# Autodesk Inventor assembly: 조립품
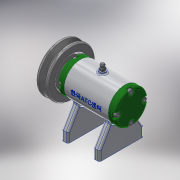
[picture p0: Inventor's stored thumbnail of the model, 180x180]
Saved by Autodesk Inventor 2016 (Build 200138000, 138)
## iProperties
Created: 2018-05
Part Number: 조립품
Material: 일반
Document SubType Name: Assembly
Designer: 201-25
Author: 201-25
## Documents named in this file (16)
- C:\Users\201-25\Desktop\480507V1001\답안조립품.iam
- C:\Users\201-25\Desktop\480507V1001\1-본체.ipt
- C:\Users\201-25\Desktop\480507V1001\베어링 6002.ipt
- C:\Users\201-25\Desktop\480507V1001\볼트 M4x12.ipt
- C:\Users\201-25\Desktop\480507V1001\볼트 M6x8.ipt
- C:\Users\201-25\Desktop\480507V1001\스프링와셔 8.ipt
- C:\Users\201-25\Desktop\480507V1001\앞커버.ipt
- C:\Users\201-25\Desktop\480507V1001\오일 실 15 25 7.ipt
- C:\Users\201-25\Desktop\480507V1001\와셔 6x11.5.ipt
- C:\Users\201-25\Desktop\480507V1001\와셔 8x17.ipt
- C:\Users\201-25\Desktop\480507V1001\축.ipt
- C:\Users\201-25\Desktop\480507V1001\키 3x3x12.ipt
- C:\Users\201-25\Desktop\480507V1001\V벨트풀리.ipt
- C:\Users\201-25\Desktop\480507V1001\너트 M8.ipt
- C:\Users\201-25\Desktop\480507V1001\니플 M6x0.75.ipt
- C:\Users\201-25\Desktop\480507V1001\뒤커버.ipt
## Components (2 placed, 2 different names)
1. 1-본체:1
2. V벨트풀리:1
